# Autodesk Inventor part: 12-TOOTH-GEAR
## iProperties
Created: 2007-09
Part Number: 12-TOOTH-GEAR
Material: ABS Plastic
Document SubType Name: Modeling
Density: 1.06 g/cm^3
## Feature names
1. Base1
